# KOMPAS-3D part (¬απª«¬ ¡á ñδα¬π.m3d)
File: created 25.07.2016 11:35:03, last saved 25.07.2016 11:36:02.
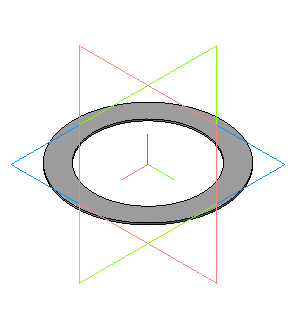
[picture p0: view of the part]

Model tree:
1. Эскиз:1
2. Операция выдавливания:1
     Толщина стенки 2 = 18; Расстояние 1 = 0.6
